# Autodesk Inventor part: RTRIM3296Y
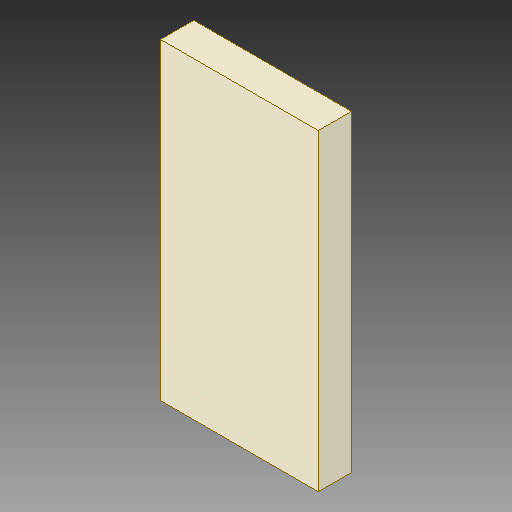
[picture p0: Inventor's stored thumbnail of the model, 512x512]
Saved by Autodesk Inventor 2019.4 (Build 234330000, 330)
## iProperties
Created: 2019-11
Part Number: RTRIM3296Y
Material: Generic
Document SubType Name: Modeling
Designer: Willist
Density: 1 g/cm^3
Appearance: RTRIM3296Y, RTRIM3296Y
Author: Willist
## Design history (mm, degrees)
sketch "RTRIM3296Y, RTRIM3296Y_128"
  geometry: L1 (-2.377, 4.777)-(2.377, 4.777); L2 (2.377, 4.777)-(2.377, -4.65); L3 (2.377, -4.65)-(-2.377, -4.65); L4 (-2.377, -4.65)-(-2.377, 4.777)
  constraints: 8 end point
extrude "Extrusion1" join sketch "RTRIM3296Y, RTRIM3296Y_128" distance "d0" = 1; taper "d1" = 0 deg
body "Solid1"
